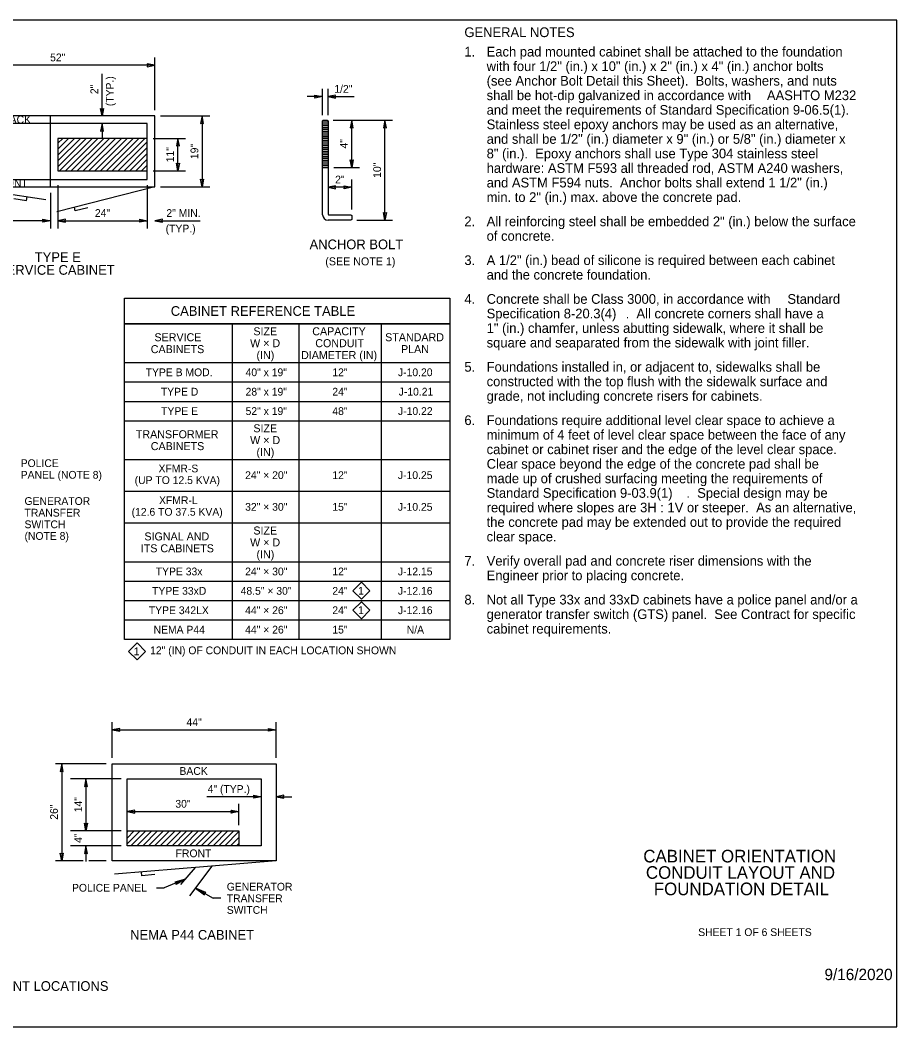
# Model space of a CAD drawing. Extents: x 99862 to 103151, y 100000 to 117076.
# Drawn here: x 101342 to 103151, y 100000 to 102076 of the extents above; entities that cross this region are included whole.
import ezdxf

# ---------------------------------------------------------------- set-up
doc = ezdxf.new("R2010")
doc.units = 0
for name, color, linetype in [('Level 1', 7, 'Continuous'), ('Level 15', 7, 'Continuous'), ('Level 20', 7, 'Continuous'), ('Level 21', 7, 'Continuous'), ('Level 25', 7, 'Continuous'), ('Level 3', 7, 'Continuous'), ('Level 4', 7, 'Continuous'), ('Level 40', 7, 'Continuous'), ('Level 60', 7, 'Continuous'), ('Level 62', 7, 'Continuous')]:
    doc.layers.add(name, color=color, linetype=linetype)

msp = doc.modelspace()

# ---------------------------------------------------------------- linework, layer by layer
at = {"layer": 'Level 1'}
msp.add_lwpolyline([(99862, 99999.5), (103151, 99999.5), (103151, 102075.5), (99862, 102075.5)], close=True, dxfattribs=at)
at = {"layer": 'Level 15'}
for p, q in [((101619.8, 101889.9), (101619.8, 101998.6)), ((101619.8, 101982.6), (101219.7, 101982.6)), ((101511.1, 101877.9), (101511.1, 101964.5)), ((101966.1, 101879.8), (101966.1, 101933.8)), ((101977.3, 101879.8), (101977.3, 101933.8)), ((101966.1, 101917.8), (101934.1, 101917.8)), ((101977.3, 101917.8), (102031.1, 101917.8)), ((101631.8, 101877.9), (101733.6, 101877.9)), ((101717.6, 101877.9), (101717.6, 101731.7)), ((101987.8, 101869.3), (102110.6, 101869.3)), ((102026.1, 101771.6), (102026.1, 101869.3)), ((102094.6, 101663.1), (102094.6, 101869.3)), ((101511.1, 101862.5), (101511.1, 101830.5)), ((101616.4, 101831.7), (101683.5, 101831.7)), ((101667.5, 101764.7), (101667.5, 101831.7)), ((101989.3, 101771.6), (102042.1, 101771.6)), ((101616.4, 101764.7), (101683.5, 101764.7)), ((102026.1, 101684.8), (102026.1, 101746.8)), ((101419.8, 101735.1), (101419.8, 101645.7)), ((101604.4, 101735.1), (101604.4, 101645.7)), ((101631.8, 101731.7), (101733.6, 101731.7)), ((102026.1, 101730.8), (101977.3, 101730.8)), ((101404.4, 101719.7), (101404.4, 101645.7)), ((102036.6, 101663.1), (102110.6, 101663.1)), ((101404.4, 101661.7), (101219.7, 101661.7)), ((101419.8, 101661.7), (101604.4, 101661.7)), ((101619.8, 101661.7), (101713.6, 101661.7)), ((101531.9, 100554), (101531.9, 100628)), ((101870.5, 100554), (101870.5, 100628)), ((101531.9, 100612), (101870.5, 100612)), ((101519.9, 100542), (101415.3, 100542)), ((101427.9, 100542), (101427.9, 100342)), ((101550.7, 100511.3), (101445.9, 100511.3)), ((101477.9, 100511.3), (101477.9, 100403.5)), ((101839.7, 100474), (101727.6, 100474)), ((101793.6, 100415.5), (101793.6, 100459.5)), ((101562.7, 100443.5), (101793.6, 100443.5)), ((101550.7, 100403.5), (101445.9, 100403.5)), ((101550.7, 100372.8), (101445.9, 100372.8)), ((101477.9, 100372.8), (101477.9, 100340.8)), ((101471.9, 100342), (101415.3, 100342)), ((101519.9, 100342), (101483.9, 100342)), ((101683.9, 100304.7), (101639.5, 100286.3)), ((101623.5, 100286.3), (101639.5, 100286.3)), ((101704.1, 100285.6), (101740.4, 100264.6)), ((101756.4, 100264.6), (101740.4, 100264.6))]:
    msp.add_line(p, q, dxfattribs=at)
for points in [[(101619.8, 101982.6), (101604.1, 101985.6), (101604.8, 101982.6), (101604.1, 101979.5)], [(101966.1, 101917.8), (101950.3, 101914.7), (101951.1, 101917.8), (101950.3, 101920.9)], [(101977.3, 101917.8), (101993, 101914.7), (101992.3, 101917.8), (101993, 101920.9)], [(101511.1, 101877.9), (101508, 101893.6), (101511.1, 101892.9), (101514.2, 101893.6)], [(101717.6, 101877.9), (101714.5, 101862.2), (101717.6, 101862.9), (101720.6, 101862.2)], [(102026.1, 101869.3), (102023, 101853.6), (102026.1, 101854.3), (102029.2, 101853.6)], [(102094.6, 101869.3), (102091.5, 101853.6), (102094.6, 101854.3), (102097.7, 101853.6)], [(101511.1, 101862.5), (101508, 101846.8), (101511.1, 101847.5), (101514.2, 101846.8)], [(101667.5, 101831.7), (101664.5, 101816), (101667.5, 101816.7), (101670.6, 101816)], [(102026.1, 101771.6), (102023, 101787.4), (102026.1, 101786.6), (102029.2, 101787.4)], [(101667.5, 101764.7), (101664.5, 101780.4), (101667.5, 101779.7), (101670.6, 101780.4)], [(101717.6, 101731.7), (101714.5, 101747.4), (101717.6, 101746.7), (101720.6, 101747.4)], [(101977.3, 101730.8), (101993, 101727.7), (101992.3, 101730.8), (101993, 101733.9)], [(102026.1, 101730.8), (102010.3, 101727.7), (102011.1, 101730.8), (102010.3, 101733.9)], [(101404.4, 101661.7), (101388.6, 101658.6), (101389.4, 101661.7), (101388.6, 101664.8)], [(101419.8, 101661.7), (101435.5, 101658.6), (101434.8, 101661.7), (101435.5, 101664.8)], [(101604.4, 101661.7), (101588.7, 101658.6), (101589.4, 101661.7), (101588.7, 101664.8)], [(101619.8, 101661.7), (101635.6, 101658.6), (101634.8, 101661.7), (101635.6, 101664.8)], [(102094.6, 101663.1), (102091.5, 101678.8), (102094.6, 101678.1), (102097.7, 101678.8)], [(101531.9, 100612), (101547.7, 100609), (101546.9, 100612), (101547.7, 100615.1)], [(101870.5, 100612), (101854.8, 100609), (101855.5, 100612), (101854.8, 100615.1)], [(101427.9, 100542), (101424.8, 100526.3), (101427.9, 100527.1), (101431, 100526.3)], [(101477.9, 100511.3), (101474.8, 100495.5), (101477.9, 100496.3), (101481, 100495.5)], [(101562.7, 100443.5), (101578.4, 100440.5), (101577.7, 100443.5), (101578.4, 100446.6)], [(101793.6, 100443.5), (101777.8, 100440.5), (101778.6, 100443.5), (101777.8, 100446.6)], [(101477.9, 100403.5), (101474.8, 100419.3), (101477.9, 100418.5), (101481, 100419.3)], [(101427.9, 100342), (101424.8, 100357.7), (101427.9, 100357), (101431, 100357.7)], [(101477.9, 100372.8), (101474.8, 100357), (101477.9, 100357.8), (101481, 100357)], [(101683.9, 100304.7), (101663.9, 100293.2), (101663.7, 100296.3), (101661.6, 100298.7)], [(101704.1, 100285.6), (101722.3, 100271.6), (101722.9, 100274.7), (101725.3, 100276.7)]]:
    msp.add_lwpolyline(points, close=True, dxfattribs=at)
at = {"layer": 'Level 20'}
msp.add_line((101870.5, 100474), (101902.5, 100474), dxfattribs=at)
for points in [[(102046.3, 100916.3), (102063.8, 100898.8), (102046.3, 100881.2), (102028.7, 100898.8)], [(102046.3, 100876.3), (102063.8, 100858.8), (102046.3, 100841.2), (102028.7, 100858.8)], [(101583.3, 100791.4), (101600.8, 100773.8), (101583.3, 100756.3), (101565.7, 100773.8)], [(101839.7, 100474), (101824, 100470.9), (101824.7, 100474), (101824, 100477.1)], [(101870.5, 100474), (101886.2, 100470.9), (101885.5, 100474), (101886.2, 100477.1)]]:
    msp.add_lwpolyline(points, close=True, dxfattribs=at)
at = {"layer": 'Level 21'}
for p, q in [((101966.1, 101867.8), (101967.6, 101869.3)), ((101967.6, 101869.3), (101975.8, 101869.3)), ((101975.8, 101869.3), (101977.3, 101867.8)), ((101966.1, 101674.3), (101966.1, 101867.8)), ((101966.1, 101865.6), (101977.3, 101865.6)), ((101966.1, 101861.8), (101977.3, 101861.8)), ((101966.1, 101858.1), (101977.3, 101858.1)), ((101966.1, 101854.3), (101977.3, 101854.3)), ((101966.1, 101850.6), (101977.3, 101850.6)), ((101977.3, 101867.8), (101977.3, 101675.5)), ((101966.1, 101846.8), (101977.3, 101846.8)), ((101966.1, 101843.1), (101977.3, 101843.1)), ((101966.1, 101839.3), (101977.3, 101839.3)), ((101966.1, 101835.6), (101977.3, 101835.6)), ((101966.1, 101831.8), (101977.3, 101831.8)), ((101966.1, 101828.1), (101977.3, 101828.1)), ((101966.1, 101824.3), (101977.3, 101824.3)), ((101966.1, 101820.6), (101977.3, 101820.6)), ((101966.1, 101816.8), (101977.3, 101816.8)), ((101966.1, 101813.1), (101977.3, 101813.1)), ((101966.1, 101809.3), (101977.3, 101809.3)), ((101966.1, 101805.6), (101977.3, 101805.6)), ((101966.1, 101801.8), (101977.3, 101801.8)), ((101966.1, 101798.1), (101977.3, 101798.1)), ((101966.1, 101794.3), (101977.3, 101794.3)), ((101966.1, 101790.6), (101977.3, 101790.6)), ((101966.1, 101786.8), (101977.3, 101786.8)), ((101966.1, 101783.1), (101977.3, 101783.1)), ((101966.1, 101779.3), (101977.3, 101779.3)), ((101966.1, 101775.6), (101977.3, 101775.6)), ((101966.1, 101771.8), (101977.3, 101771.8)), ((102024.6, 101663.1), (101977.3, 101663.1)), ((101978.4, 101674.3), (102024.6, 101674.3)), ((102024.6, 101674.3), (102026.1, 101672.8)), ((102026.1, 101664.6), (102024.6, 101663.1)), ((102026.1, 101672.8), (102026.1, 101664.6))]:
    msp.add_line(p, q, dxfattribs=at)
for centre, radius in [((101977.3, 101674.3), 11.2), ((101978.4, 101675.5), 1.12)]:
    msp.add_arc(centre, radius, 180, 270, dxfattribs=at)
at = {"layer": 'Level 25'}
for p, q in [((101604.4, 101831.7), (101419.8, 101831.7)), ((101419.8, 101831.7), (101419.8, 101764.7)), ((101419.8, 101821.5), (101430, 101831.7)), ((101419.8, 101809.4), (101442.1, 101831.7)), ((101419.8, 101797.3), (101454.2, 101831.7)), ((101419.8, 101785.3), (101466.3, 101831.7)), ((101419.8, 101773.2), (101478.3, 101831.7)), ((101423.4, 101764.7), (101490.4, 101831.7)), ((101435.5, 101764.7), (101502.5, 101831.7)), ((101447.6, 101764.7), (101514.6, 101831.7)), ((101459.7, 101764.7), (101526.7, 101831.7)), ((101471.8, 101764.7), (101538.8, 101831.7)), ((101483.9, 101764.7), (101550.9, 101831.7)), ((101495.9, 101764.7), (101563, 101831.7)), ((101508, 101764.7), (101575.1, 101831.7)), ((101520.1, 101764.7), (101587.2, 101831.7)), ((101532.2, 101764.7), (101599.3, 101831.7)), ((101544.3, 101764.7), (101604.4, 101824.8)), ((101556.4, 101764.7), (101604.4, 101812.7)), ((101568.5, 101764.7), (101604.4, 101800.7)), ((101580.6, 101764.7), (101604.4, 101788.6)), ((101592.7, 101764.7), (101604.4, 101776.5)), ((101419.8, 101764.7), (101604.4, 101764.7)), ((101562.7, 100403.5), (101793.6, 100403.5)), ((101562.7, 100401), (101565.2, 100403.5)), ((101562.7, 100388.9), (101577.3, 100403.5)), ((101562.7, 100376.8), (101589.4, 100403.5)), ((101570.7, 100372.8), (101601.5, 100403.5)), ((101582.8, 100372.8), (101613.6, 100403.5)), ((101594.9, 100372.8), (101625.7, 100403.5)), ((101607, 100372.8), (101637.8, 100403.5)), ((101619.1, 100372.8), (101649.9, 100403.5)), ((101631.2, 100372.8), (101662, 100403.5)), ((101643.3, 100372.8), (101674.1, 100403.5)), ((101655.4, 100372.8), (101686.2, 100403.5)), ((101667.5, 100372.8), (101698.2, 100403.5)), ((101679.6, 100372.8), (101710.3, 100403.5)), ((101691.6, 100372.8), (101722.4, 100403.5)), ((101703.7, 100372.8), (101734.5, 100403.5)), ((101715.8, 100372.8), (101746.6, 100403.5)), ((101727.9, 100372.8), (101758.7, 100403.5)), ((101740, 100372.8), (101770.8, 100403.5)), ((101752.1, 100372.8), (101782.9, 100403.5)), ((101764.2, 100372.8), (101793.6, 100402.1)), ((101793.6, 100403.5), (101793.6, 100372.8)), ((101776.3, 100372.8), (101793.6, 100390)), ((101788.4, 100372.8), (101793.6, 100377.9)), ((101792.9, 100372.8), (101793.6, 100373.4))]:
    msp.add_line(p, q, dxfattribs=at)
at = {"layer": 'Level 3'}
for p, q in [((101404.4, 101731.7), (101404.4, 101877.9)), ((101219.7, 101731.7), (101395.3, 101705.4)), ((101619.8, 101731.7), (101417.5, 101680.2)), ((101328.8, 101707.6), (101355.4, 101703.6)), ((101355.4, 101703.6), (101356.6, 101711.2)), ((101455.8, 101682), (101453.9, 101689.5)), ((101481.9, 101688.6), (101455.8, 101682))]:
    msp.add_line(p, q, dxfattribs=at)
for points in [[(101219.7, 101731.7), (101619.8, 101731.7), (101619.8, 101877.9), (101219.7, 101877.9)], [(101235.1, 101747.1), (101604.4, 101747.1), (101604.4, 101862.5), (101235.1, 101862.5)]]:
    msp.add_lwpolyline(points, close=True, dxfattribs=at)
at = {"layer": 'Level 4'}
for p, q in [((101870.5, 100342), (101536.8, 100314.2)), ((101593.3, 100311.2), (101592.7, 100318.8)), ((101620.2, 100313.4), (101593.3, 100311.2)), ((101673.8, 100292.8), (101703.7, 100328.1)), ((101692.3, 100269.9), (101738.2, 100331))]:
    msp.add_line(p, q, dxfattribs=at)
for points in [[(101531.9, 100542), (101870.5, 100542), (101870.5, 100342), (101531.9, 100342)], [(101562.7, 100511.3), (101839.7, 100511.3), (101839.7, 100372.8), (101562.7, 100372.8)]]:
    msp.add_lwpolyline(points, close=True, dxfattribs=at)
at = {"layer": 'Level 40'}
for p, q in [((101779.4, 101449.3), (101779.4, 100798.6)), ((101917.3, 101449.3), (101917.3, 100798.6)), ((102086.8, 101449.3), (102086.8, 100798.6)), ((101557.7, 101369.3), (102228.4, 101369.3)), ((101557.7, 101329.3), (102228.4, 101329.3)), ((101557.7, 101289.3), (102228.4, 101289.3)), ((101557.7, 101249.3), (102228.4, 101249.3)), ((101557.7, 101169.3), (102228.4, 101169.3)), ((101557.7, 101103.9), (102228.4, 101103.9)), ((101557.7, 101038.6), (102228.4, 101038.6)), ((101557.7, 100958.6), (102228.4, 100958.6)), ((101557.7, 100918.6), (102228.4, 100918.6)), ((101557.7, 100878.6), (102228.4, 100878.6)), ((101557.7, 100838.6), (102228.4, 100838.6))]:
    msp.add_line(p, q, dxfattribs=at)
for points in [[(101557.7, 101502), (102228.4, 101502), (102228.4, 101449.3), (101557.7, 101449.3)], [(101557.7, 101449.3), (102228.4, 101449.3), (102228.4, 100798.6), (101557.7, 100798.6)]]:
    msp.add_lwpolyline(points, close=True, dxfattribs=at)
at = {"layer": 'Level 60'}
msp.add_line((103151, 102075.5), (103151, 102075.5), dxfattribs=at)

# ---------------------------------------------------------------- texts
at = {"layer": 'Level 15'}
msp.add_text('9/16/2020', height=23.62, dxfattribs=at).set_placement((103001.6, 100095.8))
at = {"layer": 'Level 20'}
for s, height, p in [('GENERAL NOTES', 20, (102258.7, 102040.5)), ('1.', 20, (102258.7, 102000.5)), ('Each pad mounted cabinet shall be attached to the foundation', 20, (102304.6, 102000.5)), ('52"', 16, (101403.9, 101990.6)), ('with four 1/2" (in.) x 10" (in.) x 2" (in.) x 4" (in.) anchor bolts', 20, (102304.6, 101970.5)), ('(see Anchor Bolt Detail this Sheet).  Bolts, washers, and nuts', 20, (102304.6, 101940.5)), ('1/2"', 16, (101990.3, 101925.8)), ('shall be hot-dip galvanized in accordance with ', 20, (102304.6, 101910.5)), ('AASHTO M232', 20, (102882.9, 101910.5)), ('and meet the requirements of Standard Specification 9-06.5(1).', 20, (102304.6, 101880.5)), ('BACK', 16, (101306.2, 101862.4)), ('Stainless steel epoxy anchors may be used as an alternative,', 20, (102304.6, 101850.5)), ('and shall be 1/2" (in.) diameter x 9" (in.) or 5/8" (in.) diameter x', 20, (102304.6, 101820.5)), ('8" (in.).  Epoxy anchors shall use Type 304 stainless steel', 20, (102304.6, 101790.5)), ('hardware: ASTM F593 all threaded rod, ASTM A240 washers,', 20, (102304.6, 101760.5)), ('FRONT', 16, (101284.2, 101731.6)), ('2"', 16, (101992, 101738.8)), ('and ASTM F594 nuts.  Anchor bolts shall extend 1 1/2" (in.)', 20, (102304.6, 101730.5)), ('min. to 2" (in.) max. above the concrete pad.', 20, (102304.6, 101700.5)), ('24"', 16, (101496.2, 101669.7)), ('2" MIN.', 16, (101643.8, 101669.7)), ('2.', 20, (102258.7, 101650.5)), ('All reinforcing steel shall be embedded 2" (in.) below the surface', 20, (102304.6, 101650.5)), ('(TYP.)', 16, (101642.3, 101637.7)), ('of concrete.', 20, (102304.6, 101620.5)), ('ANCHOR BOLT', 20, (101939.2, 101603.1)), ('TYPE E', 20, (101372.2, 101576.8)), ('(SEE NOTE 1)', 16.5, (101971.7, 101569.8)), ('3.', 20, (102258.7, 101570.5)), ('A 1/2" (in.) bead of silicone is required between each cabinet', 20, (102304.6, 101570.5)), ('SERVICE CABINET', 20, (101296.4, 101550.4)), ('and the concrete foundation.', 20, (102304.6, 101540.5)), ('4.', 20, (102258.7, 101490.5)), ('Concrete shall be Class 3000, in accordance with ', 20, (102304.6, 101490.5)), ('Standard', 20, (102925.2, 101490.5)), ('CABINET REFERENCE TABLE', 20, (101652.9, 101465.7)), ('Specification 8-20.3(4)', 20, (102304.6, 101460.5)), ('.  All concrete corners shall have a', 20, (102591.4, 101460.5)), ('SIZE', 16.5, (101823.3, 101425.6)), ('CAPACITY', 16.5, (101944.8, 101425.6)), ('1" (in.) chamfer, unless abutting sidewalk, where it shall be', 20, (102304.6, 101430.5)), ('SERVICE', 16.5, (101619.2, 101413.3)), ('W × D', 16.5, (101816.6, 101401.1)), ('CONDUIT', 16.5, (101951, 101401.1)), ('STANDARD', 16.5, (102095.2, 101413.3)), ('square and seaparated from the sidewalk with joint filler.', 20, (102304.6, 101400.5)), ('CABINETS', 16.5, (101611.6, 101388.8)), ('(IN)', 16.5, (101829.7, 101376.6)), ('DIAMETER (IN)', 16.5, (101921.7, 101376.6)), ('PLAN', 16.5, (102127.9, 101388.8)), ('Foundations installed in, or adjacent to, sidewalks shall be', 20, (102304.6, 101350.5)), ('TYPE B MOD.', 16, (101601.1, 101341.3)), ('40" x 19"', 16, (101807.2, 101341.3)), ('12"', 16, (101986.2, 101341.3)), ('J-10.20', 16, (102121.6, 101341.3)), ('5.', 20, (102258.7, 101350.5)), ('constructed with the top flush with the sidewalk surface and', 20, (102304.6, 101320.5)), ('TYPE D', 16, (101632.4, 101301.3)), ('28" x 19"', 16, (101807.2, 101301.3)), ('24"', 16, (101986.2, 101301.3)), ('J-10.21', 16, (102123.1, 101301.3)), ('grade, not including concrete risers for cabinets.', 20, (102304.6, 101290.5)), ('TYPE E', 16, (101633, 101261.3)), ('52" x 19"', 16, (101807.2, 101261.3)), ('48"', 16, (101986.2, 101261.3)), ('J-10.22', 16, (102121.7, 101261.3)), ('6.', 20, (102258.7, 101240.5)), ('Foundations require additional level clear space to achieve a', 20, (102304.6, 101240.5)), ('TRANSFORMER', 16.5, (101580.8, 101213.3)), ('SIZE', 16.5, (101823.3, 101225.6)), ('minimum of 4 feet of level clear space between the face of any', 20, (102304.6, 101210.5)), ('CABINETS', 16.5, (101611.6, 101188.8)), ('W × D', 16.5, (101816.6, 101201.1)), ('(IN)', 16.5, (101829.7, 101176.6)), ('cabinet or cabinet riser and the edge of the level clear space.', 20, (102304.6, 101180.5)), ('POLICE', 16, (101343.2, 101153.9)), ('Clear space beyond the edge of the concrete pad shall be', 20, (102304.6, 101150.5)), ('PANEL (NOTE 8)', 16, (101343.2, 101129.9)), ('XFMR-S', 16, (101627.6, 101142.9)), ('24" × 20"', 16, (101806.3, 101129.2)), ('12"', 16, (101986.2, 101129.2)), ('J-10.25', 16, (102121.5, 101129.2)), ('(UP TO 12.5 KVA)', 16, (101578.4, 101118.9)), ('made up of crushed surfacing meeting the requirements of', 20, (102304.6, 101120.5)), ('Standard Specification 9-03.9(1)', 20, (102304.6, 101090.5)), ('.  Special design may be', 20, (102716.7, 101090.5)), ('XFMR-L', 16, (101628.7, 101077.5)), ('required where slopes are 3H : 1V or steeper.  As an alternative,', 20, (102304.6, 101060.5)), ('(12.6 TO 37.5 KVA)', 16, (101572.1, 101053.5)), ('32" × 30"', 16, (101806.3, 101063.8)), ('15"', 16, (101986.2, 101063.8)), ('J-10.25', 16, (102121.5, 101063.8)), ('the concrete pad may be extended out to provide the required', 20, (102304.6, 101030.5)), ('SIGNAL AND', 16.5, (101598.5, 101002.6)), ('SIZE', 16.5, (101823.3, 101014.8)), ('clear space.', 20, (102304.6, 101000.5)), ('W × D', 16.5, (101816.6, 100990.3)), ('ITS CABINETS', 16.5, (101591, 100978.1)), ('(IN)', 16.5, (101829.7, 100965.8)), ('7.', 20, (102258.7, 100950.5)), ('Verify overall pad and concrete riser dimensions with the', 20, (102304.6, 100950.5)), ('TYPE 33x', 16, (101621.9, 100930.6)), ('24" × 30"', 16, (101806.3, 100930.6)), ('12"', 16, (101986.2, 100930.6)), ('J-12.15', 16, (102121.5, 100930.6)), ('Engineer prior to placing concrete.', 20, (102304.6, 100920.5)), ('TYPE 33xD', 16, (101614.4, 100890.6)), ('48.5" × 30"', 16, (101797, 100890.6)), ('24"', 16, (101986.2, 100890.6)), ('1', 16, (102039.3, 100890.8)), ('J-12.16', 16, (102121.6, 100890.6)), ('8.', 20, (102258.7, 100870.5)), ('Not all Type 33x and 33xD cabinets have a police panel and/or a', 20, (102304.6, 100870.5)), ('TYPE 342LX', 16, (101607.6, 100850.6)), ('44" × 26"', 16, (101806.3, 100850.6)), ('24"', 16, (101986.2, 100850.6)), ('1', 16, (102039.3, 100850.8)), ('J-12.16', 16, (102121.6, 100850.6)), ('generator transfer switch (GTS) panel.  See Contract for specific', 20, (102304.6, 100840.5)), ('cabinet requirements.', 20, (102304.6, 100810.5)), ('NEMA P44', 16, (101617.4, 100810.6)), ('44" × 26"', 16, (101806.3, 100810.6)), ('15"', 16, (101986.2, 100810.6)), ('N/A', 16, (102139.7, 100810.6)), ('1', 16, (101576.3, 100765.8)), ('12" (IN) OF CONDUIT IN EACH LOCATION SHOWN', 16, (101610.2, 100767.9)), ('44"', 16, (101685.4, 100620)), ('BACK', 16, (101670.8, 100519.1)), ('4" (TYP.)', 16, (101728.9, 100482)), ('30"', 16, (101662.3, 100451.5)), ('FRONT', 16, (101662.9, 100349.4)), ('POLICE PANEL', 16, (101449.1, 100278.3)), ('NEMA P44 CABINET', 20, (101569.1, 100179.3)), ('CABINET ORIENTATION, FOOTPRINT, AND CONDUIT PLACEMENT LOCATIONS', 20, (100515.4, 100073.7))]:
    msp.add_text(s, height=height, dxfattribs=at).set_placement(p)
for s, rotation, p in [('(TYP.)', 90, (101535.1, 101898.1)), ('2"', 90, (101503.1, 101922.9)), ('4"', 90, (102018.1, 101810.8)), ('11"', 90, (101659.5, 101782.4)), ('19"', 90, (101709.6, 101788.9)), ('10"', 90, (102086.6, 101750.3)), ('GENERATOR', 360, (101351.1, 101075.8)), ('TRANSFER', 360, (101351.1, 101051.8)), ('SWITCH', 360, (101351.1, 101027.8)), ('(NOTE 8)', 360, (101351.1, 101003.8)), ('14"', 90, (101469.9, 100442)), ('26"', 90, (101419.9, 100426.6)), ('4"', 90, (101469.9, 100378.8)), ('GENERATOR', 360, (101768.4, 100280.6)), ('TRANSFER', 360, (101768.4, 100256.6)), ('SWITCH', 360, (101768.4, 100232.6))]:
    msp.add_text(s, height=16, rotation=rotation, dxfattribs=at).set_placement(p)
at = {"layer": 'Level 62'}
for s, height, p in [('CABINET ORIENTATION', 26, (102627.8, 100338.6)), ('CONDUIT LAYOUT AND', 26, (102633.2, 100304.8)), ('FOUNDATION DETAIL', 26, (102649.6, 100271)), ('SHEET 1 OF 6 SHEETS', 16, (102741.1, 100186.8))]:
    msp.add_text(s, height=height, dxfattribs=at).set_placement(p)

doc.saveas('drawing.dxf')
